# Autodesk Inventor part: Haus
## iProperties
Shininess: 64.0
Length Units: 11269
Angle Units: 11279
Time Units: 11290
Mass Units: 11283
Length Display Precision: 3
Angle Display Precision: 3
Compacted: True
Part Number: Haus
Document SubType Name: Modeling
Created: 2003-12
Material: Standard
Designer: HAH
Manufacturer: Standard
Standards Organization: Custom
Density: 0.0
Volumn: 0.0
Area: 0.0
PropertySet Name: Model Information
Control State: 0
Master: False
Checked Out: False
d0: 250,000 mm
d1: 180,000 mm
d4: 8,000 mm
d7: 12,000 mm
d9: 90,000 grd
d10: 32,000 mm
d11: 10,000 mm
d12: 100,000 mm
d13: 20,000 mm
d14: 25,000 grd
d15: 30,000 mm
d16: 10,000 mm
d17: 35,000 mm
Author: HAH
